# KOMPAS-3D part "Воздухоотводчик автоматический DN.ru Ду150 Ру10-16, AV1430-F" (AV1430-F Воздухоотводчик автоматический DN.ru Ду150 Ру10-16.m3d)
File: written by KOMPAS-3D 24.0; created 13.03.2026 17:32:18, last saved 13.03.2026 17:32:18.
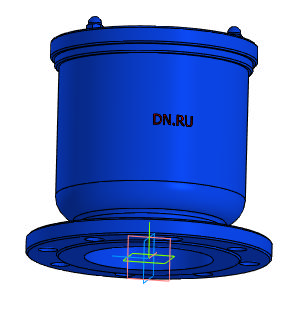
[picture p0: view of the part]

Document properties: Автор: R2D2; Полное имя файла: E:\Работа\Зайцев\AV1430-F Воздухоотводчик автоматический DN.ru Ру10-16 (1)\AV1430-F Воздухоотводчик автоматический DN.ru Ру10-16\DN150\AV1430-F Воздухоотводчик автоматический DN.ru Ду150 Ру10-16.m3d

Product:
- Part/product: Воздухоотводчик автоматический DN.ru Ду150 Ру10-16  | designation AV1430-F
    Масса: 22
    Раздел спецификации: Прочие изделия
    Примечание: D030-00257

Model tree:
1. Операция без истории:1

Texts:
  AV1430-F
